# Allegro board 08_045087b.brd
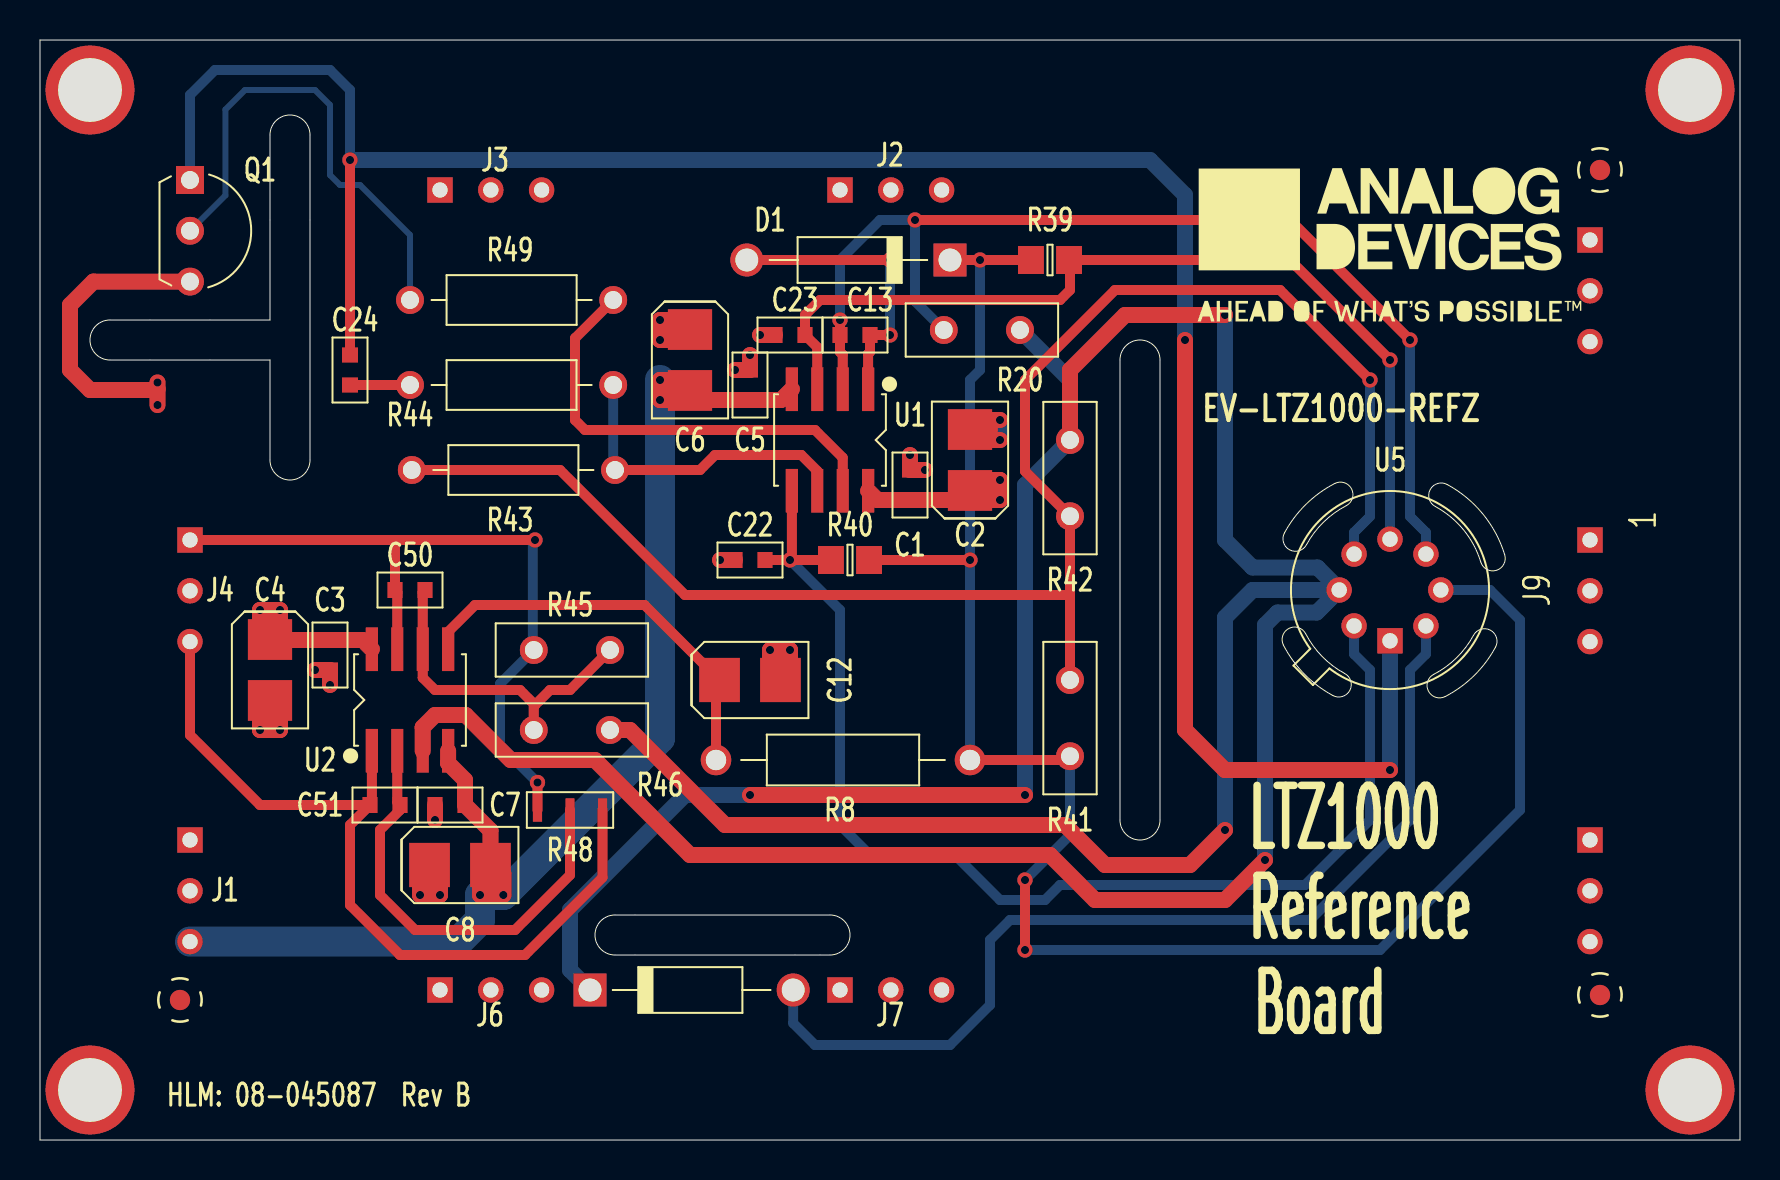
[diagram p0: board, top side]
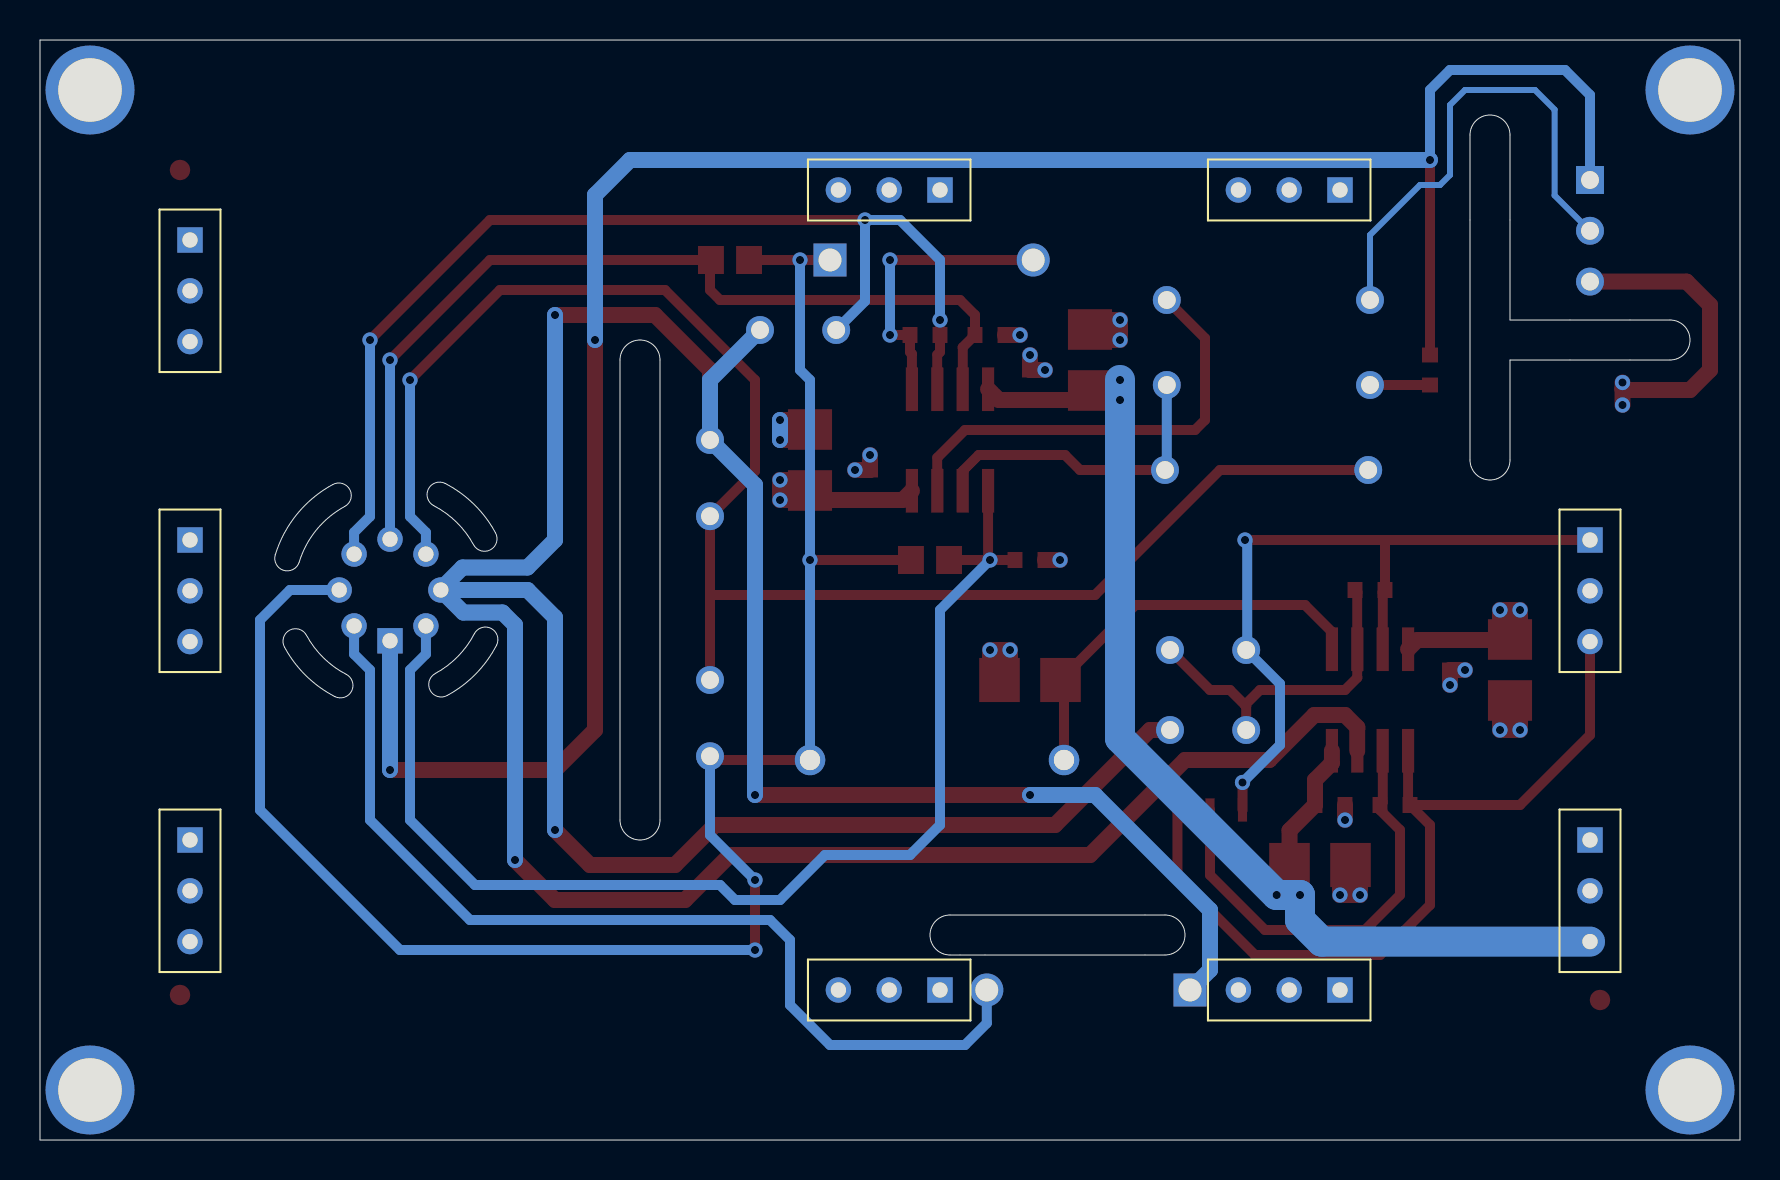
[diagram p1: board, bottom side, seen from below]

Outline 85 x 55 mm; copper layers: TOP, LAYER2, LAYER3, BOTTOM. Coordinates in mm from the lower left corner of the outline.
Outline path: 0,55 0,0 85,0 85,55 0,55 ; 3.5,39 arc(2.5,40) 3.5,41 11.5,41 11.5,50.25 arc(12.5,51.25) 13.5,50.25 13.5,34 arc(13.21,33.29) 12.5,33 arc(11.79,33.29) 11.5,34 11.5,39 3.5,39 ; 28.75,11.25 39.5,11.25 arc(40.5,10.25) 39.5,9.25 28.75,9.25 arc(27.75,10.25) 28.75,11.25 ; 54,39 54,16 arc(54.29,15.29) 55,15 arc(55.71,15.29) 56,16 56,39 arc(55.71,39.71) 55,40 arc(54.29,39.71) 54,39 ; 62.17,24.74 arc(62.44,25.58) 63.28,25.31 arc(64.11,24.17) 65.24,23.32 arc(65.49,22.48) 64.64,22.22 arc(63.22,23.3) 62.17,24.74 62.17,24.74 ; 62.22,30.36 arc(63.3,31.78) 64.74,32.83 64.74,32.83 arc(65.58,32.56) 65.31,31.72 arc(64.17,30.89) 63.32,29.76 arc(62.48,29.51) 62.22,30.36 ; 69.76,31.68 arc(69.51,32.52) 70.36,32.78 arc(72.14,31.3) 73.23,29.26 arc(72.82,28.48) 72.04,28.9 arc(71.17,30.51) 69.76,31.68 ; 70.26,22.17 arc(69.42,22.44) 69.69,23.28 arc(70.83,24.11) 71.68,25.24 arc(72.52,25.49) 72.78,24.64 arc(71.7,23.22) 70.26,22.17 70.26,22.17

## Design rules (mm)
constraint set DEFAULT: min track width 0.19

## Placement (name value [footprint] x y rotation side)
C1  0.1UF  [C0603]  43.5 32.75 270 top
C2  10uF  [C3528]  46.5 34 90 top
C3  0.1UF  [C0603]  14.5 24.25 90 top
C4  10uF  [C3528]  11.5 23.5 270 top
C5  0.1UF  [C0603]  35.5 37.75 90 top
C6  10uF  [C3528]  32.5 39 270 top
C7  0.1UF  [C0603]  20.5 16.75 180 top
C8  10uF  [C3528]  21 13.75 0 top
C12  10uF  [C3528]  35.5 23 0 top
C13  0.1UF  [C0603]  40.75 40.25 0 top
C22  0.1UF  [C0603]  35.5 29 0 top
C23  0.1UF  [C0603]  37.5 40.25 0 top
C24  0.1UF  [C0603]  15.5 38.5 90 top
C50  0.1UF  [C0603]  18.5 27.5 180 top
C51  0.1UF  [C0603]  17.25 16.75 180 top
D1  1N270  [DO35]  45.5 44 180 top
D2  1N270  [DO35]  27.5 7.5 0 top
J1  350-10-103-00-006000  [CNTHMHDR1X3L300W100H284]  7.5 15 270 bottom
J2  350-10-103-00-006000  [CNTHMHDR1X3L300W100H284]  40 47.5 0 bottom
J3  350-10-103-00-006000  [CNTHMHDR1X3L300W100H284]  20 47.5 0 bottom
J4  310-13-103-41-001000  [CNTHFHDR1X3L300W100H165]  7.5 30 270 bottom
J5  310-13-103-41-001000  [CNTHFHDR1X3L300W100H165]  77.5 45 270 bottom
J6  310-13-103-41-001000  [CNTHFHDR1X3L300W100H165]  20 7.5 0 bottom
J7  350-10-103-00-006000  [CNTHMHDR1X3L300W100H284]  40 7.5 0 bottom
J8  350-10-103-00-006000  [CNTHMHDR1X3L300W100H284]  77.5 15 270 bottom
J9  350-10-103-00-006000  [CNTHMHDR1X3L300W100H284]  77.5 30 270 bottom
NOREF  -  []  55 15 90 top
NOREF#2  -  [unnamed#2]  82.5 52.5 0 top
NOREF#3  -  []  0 55 0 top
NOREF#4  -  []  -100 -90 0 top
NOREF#5  -  []  54 39 0 top
NOREF#6  -  []  28.75 9.25 90 top
NOREF#7  -  []  -95 -90 0 top
NOREF#8  -  [unnamed#2]  82.5 2.5 0 top
NOREF#9  -  []  27.75 10.25 0 top
NOREF#10  -  [unnamed#2]  78 7.25 0 top
NOREF#11  -  [unnamed#2]  2.5 52.5 0 top
NOREF#12  -  []  11.5 46 0 top
NOREF#13  -  [unnamed#2]  2.5 2.5 0 top
NOREF#14  -  [unnamed#2]  78 48.5 0 top
NOREF#15  -  []  41.75 -11.25 0 top
NOREF#16  -  []  0 0 90 top
NOREF#17  -  []  67.5 44.75 0 top
NOREF#18  -  [unnamed#2]  7 7 0 top
Q1  2N3904TF  [TO92V2]  7.5 48 270 top
R8  1.5K  [RN55]  46.5 19 180 top
R20  120  [RRADTH150L300H336W105LD25]  49 40.5 180 top
R39  68K  [R0805]  50.5 44 180 top
R40  68K  [R0805]  40.5 29 0 top
R41  15K  [RRADTH150L300H336W105LD25]  51.5 23 270 top
R42  1K  [RRADTH150L300H336W105LD25]  51.5 35 270 top
R43  10K  [MRS25]  28.75 33.5 180 top
R44  1MEG  [MRS25]  18.5 37.75 0 top
R45  10K  [RRADTH150L300H336W105LD25]  28.5 24.5 180 top
R46  25K  [RRADTH150L300H336W105LD25]  28.5 20.5 180 top
R48  10K/10K  [R1505_A]  26.5 16.5 0 top
R49  1K  [MRS25]  18.5 42 0 top
U1  ADA4077-2BRZ  [SO8]  39.5 35 180 top
U2  ADA4077-2BRZ  [SO8]  18.5 22 0 top
U5  LTZ1000ACH#PBF  [TO5-8P]  67.5 27.5 180 top

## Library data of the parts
C1 C3 C5 C7 C13 C22-C24 C50 C51 = CAP: User Part Number: UPN; Tolerance: 10; alternate symbols: (); part number: CAP_SM-0.1UF,25V,10,E007204,C0603; tolerance: 10
C2 C4 C6 C8 C12 = CAPP: User Part Number: UPN; Tolerance: N/A; alternate symbols: (); part number: CAPP_SM-10UF,N/A,N/A,E000695,C3528; tolerance: N/A
D1 D2 = DIO: Tolerance: N/A; User Part Number: UPN; alternate symbols: (); part number: DIO_TH-1N270,N/A,N/A,E001093,DO35; tolerance: N/A
J1-J3 J7-J9 = CN3P: User Part Number: UPN; Tolerance: N/A; alternate symbols: (); part number: CN3P_TH-350-10-103-00-006000,E027762,CNTHMHDR1X3L300W100H284; tolerance: N/A
J4-J6 = CN3P: User Part Number: UPN; Tolerance: N/A; alternate symbols: (); part number: CN3P_TH-310-13-103-41-001000,E027752,CNTHFHDR1X3L300W100H165; tolerance: N/A
Q1 = TRAN2N3904: User Part Number: UPN; Tolerance: N/A; alternate symbols: (); part number: TRAN2N3904_TH-2N3904TF,E017741,TO92V2; tolerance: N/A
R8 = RES: Tolerance: 1; User Part Number: UPN; alternate symbols: (); part number: RES_TH-1.5K,E002827,1/4W,1,RN55; tolerance: 1
R20 = RES: Tolerance: 0.01; User Part Number: UPN; alternate symbols: (); part number: RES_TH-120,E024765,3/5W,0.01,RRADTH150L300H336W105LD25; tolerance: 0.01
R39 R40 = RES: User Part Number: UPN; Tolerance: 0.1; alternate symbols: (R0805L); part number: RES_SM-68K,E024854,1/10W,0.1,R0805; tolerance: 0.1
R41 = RES: Tolerance: 0.01; User Part Number: UPN; alternate symbols: (); part number: RES_TH-15K,E024961,3/5W,0.01,RRADTH150L300H336W105LD25; tolerance: 0.01
R42 = RES: Tolerance: 0.01; User Part Number: UPN; alternate symbols: (); part number: RES_TH-1K,E024763,3/5W,0.01,RRADTH150L300H336W105LD25; tolerance: 0.01
R43 = RES: Tolerance: 1; User Part Number: UPN; alternate symbols: (); part number: RES_TH-10K,E012142,3/5W,1,MRS25; tolerance: 1
R44 = RES: Tolerance: 1; User Part Number: UPN; alternate symbols: (); part number: RES_TH-1MEG,E010720,3/5W,1,MRS25; tolerance: 1
R45 = RES: Tolerance: 0.005; User Part Number: UPN; alternate symbols: (); part number: RES_TH-10K,E018578,6/10W,0.005,RRADTH150L300H336W105LD25; tolerance: 0.005
R46 = RES: Tolerance: 0.01; User Part Number: UPN; alternate symbols: (); part number: RES_TH-25K,E024766,3/5W,0.01,RRADTH150L300H336W105LD25; tolerance: 0.01
R48 = RES3P_V2: User Part Number: UPN; Tolerance: 0.01; alternate symbols: (); part number: RES3P_V2_SM-10K/10K,E024769,1/10W,0.01,R1505_A; tolerance: 0.01
R49 = RES: Tolerance: 1; User Part Number: UPN; alternate symbols: (); part number: RES_TH-1K,E011314,3/5W,1,MRS25; tolerance: 1
U1 U2 = ADA4077_2: User Part Number: UPN; Tolerance: N/A; alternate symbols: (); part number: ADA4077_2_SM-ADA4077-2BRZ,E018506,SO8; tolerance: N/A
U5 = LINLTZ1000: User Part Number: UPN; Tolerance: N/A; alternate symbols: (); part number: LINLTZ1000_TH-LTZ1000ACH#PBF,E010783,TO5-8P; tolerance: N/A

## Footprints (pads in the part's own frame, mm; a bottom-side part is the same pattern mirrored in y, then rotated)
C0603
  rect 0.75x0.8 smd: 1(-0.75,0) 2(0.75,0)
C3528
  rect 2.032x2.21 smd: N(1.524,0) P(-1.524,0)
CNTHFHDR1X3L300W100H165
  rect 1.27x1.27 hole 0.762: 1(0,0)
  round 1.27 hole 0.762: 2(2.54,0) 3(5.08,0)
CNTHMHDR1X3L300W100H284
  rect 1.27x1.27 hole 0.762: 1(0,0)
  round 1.27 hole 0.762: 2(2.54,0) 3(5.08,0)
DO35
  round 1.651 hole 1.143: A(10.16,0)
  rect 1.651x1.651 hole 1.143: C(0,0)
MRS25
  round 1.397 hole 0.889: 1(0,0) 2(10.16,0)
R0805
  rect 1.295x1.397 smd: 1(-0.953,0) 2(0.953,0)
R1505_A
  rect 0.457x1.168 smd: 1(-1.626,0) 2(0,0) 3(1.626,0)
RN55
  round 1.524 hole 1.016: 1(0,0) 2(12.7,0)
RRADTH150L300H336W105LD25
  round 1.397 hole 0.889: 1(0,0) 2(3.81,0)
SO8
  rect 0.61x2.184 smd: 1(-1.905,-2.54) 2(-0.635,-2.54) 3(0.635,-2.54) 4(1.905,-2.54) 5(1.905,2.54) 6(0.635,2.54) 7(-0.635,2.54) 8(-1.905,2.54)
TO5-8P
  rect 1.27x1.27 hole 0.762: 1(0,2.54)
  round 1.27 hole 0.762: 2(-1.796,1.796) 3(-2.54,0) 4(-1.796,-1.796) 5(0,-2.54) 6(1.796,-1.796) 7(2.54,0) 8(1.796,1.796)
TO92V2
  rect 1.397x1.397 hole 0.889: 1(0,0)
  round 1.397 hole 0.889: 2(2.54,0) 3(5.08,0)
unnamed#2
  round 4.445 hole 3.175 unplated: (0,0)

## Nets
AGND: C1.1(N1) C2.N(N2) C3.1(N1) C4.N(N2) C5.2(N2) C6.P(N1) C7.2(N2) C8.P(N1) C12.N(N2) C22.1(N1) C23.1(N1) D2.C(N) J1.2(N2) J4.2(N2) R20.1(N1) R42.1(N1) R46.1(N1) U2.3(+IN) U5.7(N7)
VDD: C1.2(N2) C2.P(N1) C3.2(N2) C4.P(N1) J1.1(N1) Q1.3(C) U1.8(V+) U2.8(V+)
VSS: C5.1(N1) C6.N(N2) C7.1(N1) C8.N(N2) J1.3(N3) U1.4(V-) U2.4(V-)
UNNAMED_2_ADA40772_I96_: C50.1(N1) R45.1(N1) R46.2(N2) U2.6(-IN)
UNNAMED_2_ADA40772_I96__1: C12.P(N1) R8.2(N2) U2.5(+IN)
UNNAMED_2_ADA40772_I97_: C51.1(N1) R48.2(N2) U2.2(-IN)
UNNAMED_2_ADA40772_I100_: C22.2(N2) R40.1(N1) U1.5(+IN) U5.8(N8)
UNNAMED_2_ADA40772_I100__1: R43.1(N1) R44.2(N2) U1.6(-IN)
UNNAMED_2_ADA40772_I100_OUT: R49.2(N2) U1.7(OUT)
UNNAMED_2_ADA40772_I101_: C23.2(N2) R39.1(N1) U1.3(+IN) U5.5(N5)
UNNAMED_2_ADA40772_I101__1: C13.1(N1) R20.2(N2) U1.2(-IN) U5.4(N4)
UNNAMED_2_ADA40772_I101_OUT: C13.2(N2) D1.A(P) U1.1(OUT)
UNNAMED_2_CAP_I20_N1: C24.1(N1) R44.1(N1)
UNNAMED_2_CAP_I20_N2: C24.2(N2) Q1.1(E) U5.1(N1)
UNNAMED_2_DIO_I28_P: D2.A(P) U5.2(N2)
UNNAMED_2_DIO_I48_N: D1.C(N) R8.1(N1) R39.2(N2) R40.2(N2) R41.2(N2) U5.3(N3)
UNNAMED_2_LINLTZ1000_I30_N6: R41.1(N1) R42.2(N2) R43.2(N2) U5.6(N6)
UNNAMED_2_RES_I21_N1: Q1.2(B) R49.1(N1)
VREFN: C51.2(N2) J4.3(N3) R48.3(N3) U2.1(OUT)
VREFP: C50.2(N2) J4.1(N1) R45.2(N2) R48.1(N1) U2.7(OUT)

Pads without a net: J2 1 2 3; J3 1 2 3; J5 1 2 3; J6 1 2 3; J7 1 2 3; J8 1 2 3; J9 1 2 3

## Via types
v1: diameter 0.762, hole 0.406, TOP to BOTTOM, 51 vias

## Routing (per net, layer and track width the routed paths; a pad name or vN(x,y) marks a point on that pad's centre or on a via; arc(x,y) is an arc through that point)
AGND: length 239.8
  TOP w0.8: C23.1 v1(36,40.25) ; U2.3 19.14,20.64 19.75,21.25 21.28,21.25 23.53,19 27.75,19 32.5,14.25 50.5,14.25 52.75,12 59.25,12 v1(61.25,14) ; 37,23.5 37.45,23.5 37.5,23.55 v1(37.5,24.5) v1(36.5,24.5) 36.5,23.55 36.55,23.5 37,23.5 ; 37,23.5 37.02,23.48 C12.N ; 11.5,21.25 11.95,21.25 12,21.2 v1(12,20.5) v1(11,20.5) 11,21.2 11.05,21.25 11.5,21.25 ; 11.5,21.25 C4.N ; v1(14.5,22.75) C3.1 v1(13.75,23.5) ; C7.2 v1(19.75,16) ; v1(59.25,15.5) 57.5,13.75 53.25,13.75 51.25,15.75 34.25,15.75 29.5,20.5 R46.1 ; 19.36,13.56 19.36,13.64 C8.P ; 19.36,13.56 19,13.2 v1(19,12.25) v1(20,12.25) 20,12.93 19.36,13.56 ; 31.52,40.52 C6.P ; 31.52,40.52 31.52,40.05 31.47,40 v1(31,40) v1(31,41) 31.47,41 31.52,40.95 31.52,40.52 ; 47.48,35.52 47.48,35.05 47.53,35 v1(48,35) ; 47.48,35.52 47.48,35.95 47.53,36 v1(48,36) ; 47.48,35.52 C2.N ; R42.1 51.5,38.5 54.25,41.25 v1(59.25,41.25) ; v1(35.5,39.25) C5.2 v1(34.75,38.5) ; v1(49.25,17.25) v1(35.5,17.25) ; v1(43.5,34.25) C1.1 v1(44.25,33.5) ; C22.1 v1(34,29)
  LAYER2 w0.39: J4.2 7.5,28.4 ; J4.2 6.56,27.46 ; J4.2 7.5,26.52 ; J4.2 8.44,27.46 ; R20.1 50,40.5 ; R20.1 49,39.5 ; R20.1 49,41.5 ; R20.1 48,40.5 ; 6.56,12.46 J1.2 ; J1.2 7.5,11.52 ; J1.2 8.44,12.46 ; J1.2 7.5,13.4
  BOTTOM w0.8: v1(48,36) v1(48,35) ; D2.C 26.5,8.5 26.5,11.5 32.25,17.25 v1(35.5,17.25) ; v1(61.25,14) 61.25,25.75 61.88,26.38 63.84,26.38 U5.7 ; U5.7 64.96,27.54 63.88,28.62 60.62,28.62 59.25,30 v1(59.25,41.25) ; U5.7 60.62,27.5 59.25,26.12 v1(59.25,15.5) ; R20.1 51.5,38 R42.1 49.25,32.75 v1(49.25,17.25)
VDD: length 38.5
  TOP w0.8: 5.88,37.55 5.83,37.5 2.5,37.5 1.5,38.5 1.5,41.75 2.67,42.92 Q1.3 ; 5.88,37.55 v1(5.88,36.75) ; 5.88,37.55 v1(5.88,37.88) ; 47.27,32.48 47.27,32.05 47.32,32 v1(48,32) v1(48,33) 47.32,33 47.27,32.95 47.27,32.48 ; 47.27,32.48 C2.P 46.02,32 C1.2 41.87,32 U1.8 ; 11.5,25.75 11.95,25.75 12,25.8 v1(12,26.5) v1(11,26.5) 11,25.8 11.05,25.75 11.5,25.75 ; 11.5,25.75 C4.P 11.52,25 C3.2 16.14,25 U2.8
  LAYER3 w0.39: J1.1 8.44,15 ; J1.1 6.56,15 ; J1.1 7.5,14.06 ; J1.1 7.5,15.94
VSS: length 67.6
  TOP w0.8: U1.4 37.05,37 C5.1 32.98,37 C6.N 31.73,37.48 ; 22.16,13.38 C8.N 22.52,15.48 C7.1 21.25,18 20.41,18.84 U2.4 ; 22.16,13.38 22,13.23 v1(22,12.25) v1(23.17,12.25) 23.17,13.33 23.12,13.38 22.16,13.38 ; 31.73,37.48 31.73,37.05 31.68,37 v1(31,37) v1(31,38) 31.68,38 31.73,37.95 31.73,37.48
  BOTTOM w1.5: v1(31,38) v1(31,37) 31,20.08 v1(23.17,12.25) v1(22,12.25) 22,11 20.92,9.92 J1.3
UNNAMED_2_ADA40772_I96_: length 16.8
  TOP w0.5: C50.1 19.14,27.39 U2.6 19.14,23.11 19.75,22.5 24,22.5 24.75,21.75 ; 24.75,21.75 25.5,22.5 26.5,22.5 R45.1 ; 24.75,21.75 24.69,21.69 R46.2
UNNAMED_2_ADA40772_I96__1: length 20.6
  TOP w0.5: U2.5 20.41,25.41 21.75,26.75 30.23,26.75 C12.P 33.8,22.82 R8.2
UNNAMED_2_ADA40772_I97_: length 22.3
  TOP w0.5: U2.2 17.86,16.89 C51.1 18,16.5 17,15.5 17,12.25 18.75,10.5 23.75,10.5 26.5,13.25 R48.2
UNNAMED_2_ADA40772_I100_: length 60.8
  TOP w0.5: U1.5 37.59,29.09 v1(37.5,29) ; v1(37.5,29) R40.1 ; v1(37.5,29) C22.2
  BOTTOM w0.5: U5.8 65.7,24.3 66.5,23.5 66.5,16 63.25,12.75 51,12.75 50.25,12 48,12 45.75,14.25 41.5,14.25 40,15.75 40,26.5 v1(37.5,29)
UNNAMED_2_ADA40772_I100__1: length 16
  TOP w0.5: U1.6 38.87,33.45 38.06,34.25 33.75,34.25 33,33.5 R43.1
  BOTTOM w0.5: R43.1 28.66,33.59 R44.2
UNNAMED_2_ADA40772_I100_OUT: length 22.6
  TOP w0.5: R49.2 26.75,40.09 26.75,36 27.25,35.5 38.75,35.5 40.13,34.12 U1.7
UNNAMED_2_ADA40772_I101_: length 46.3
  TOP w0.5: v1(67.5,39) 62.5,44 R39.1 51.5,43.95 51.5,42.5 51,42 39,42 38.25,41.25 C23.2 38.87,39.63 U1.3
  BOTTOM w0.5: v1(67.5,39) U5.5
UNNAMED_2_ADA40772_I101__1: length 55.5
  TOP w0.5: v1(68.5,40) 62.5,46 v1(43.75,46) ; v1(40,41) C13.1 40,39.4 40.13,39.27 U1.2
  BOTTOM w0.5: U5.4 69.3,30.38 68.5,31.18 v1(68.5,40) ; v1(40,41) 40,44 42,46 v1(43.75,46) 43.75,41.94 R20.2
UNNAMED_2_ADA40772_I101_OUT: length 14.7
  TOP w0.5: v1(42.5,44) D1.A ; U1.1 41.41,39.3 41.5,39.4 C13.2 v1(42.5,40.25)
  BOTTOM w0.5: v1(42.5,40.25) v1(42.5,44)
UNNAMED_2_CAP_I20_N1: length 3
  TOP w0.5: C24.1 R44.1
UNNAMED_2_CAP_I20_N2: length 113.2
  TOP w0.5: C24.2 v1(15.5,49)
  TOP w0.8: v1(57.25,40) 57.25,20.5 59.25,18.5 v1(67.5,18.5)
  BOTTOM w0.5: v1(15.5,49) 15.5,52.5 14.5,53.5 8.75,53.5 7.5,52.25 Q1.1
  BOTTOM w0.8: U5.1 v1(67.5,18.5) ; v1(15.5,49) 55.5,49 57.25,47.25 v1(57.25,40)
UNNAMED_2_DIO_I28_P: length 49.5
  BOTTOM w0.5: U5.2 69.3,24.3 68.5,23.5 68.5,16 63.5,11 48.5,11 47.5,10 47.5,6.75 45.5,4.75 38.75,4.75 37.66,5.84 D2.A
UNNAMED_2_DIO_I48_N: length 91.7
  TOP w0.5: R41.2 51.31,19 R8.1 ; v1(49.25,13) v1(49.25,9.5) ; R39.2 v1(47,44) D1.C ; R40.2 v1(46.5,29)
  BOTTOM w0.5: v1(49.25,9.5) 67,9.5 74,16.5 74,26 72.5,27.5 U5.3 ; v1(49.25,13) 51.5,15.25 R41.2 ; v1(47,44) 47,38.5 46.5,38 v1(46.5,29) R8.1
UNNAMED_2_LINLTZ1000_I30_N6: length 81.4
  TOP w0.5: v1(66.5,38) 62,42.5 53.75,42.5 49.25,38 49.25,33.44 R42.2 51.5,27.25 ; 51.5,27.25 R41.1 ; 51.5,27.25 32.25,27.25 26,33.5 R43.2
  BOTTOM w0.5: U5.6 65.7,30.38 66.5,31.18 v1(66.5,38)
UNNAMED_2_RES_I21_N1: length 24.7
  BOTTOM w0.3: R49.1 18.5,45.25 16,47.75 15,47.75 14.5,48.25 14.5,51.75 13.75,52.5 10.25,52.5 9.27,51.52 9.27,47.23 Q1.2
VREFN: length 41.9
  TOP w0.5: R48.3 28.13,13.13 24.25,9.25 18,9.25 15.5,11.75 15.5,15.75 C51.2 ; C51.2 11,16.75 7.5,20.25 J4.3 ; C51.2 16.59,16.84 U2.1
VREFP: length 37.8
  TOP w0.5: R48.1 v1(24.87,17.88) ; 17.75,30 C50.2 17.86,27.39 U2.7 ; 17.75,30 v1(24.75,30) ; 17.75,30 J4.1
  BOTTOM w0.5: v1(24.87,17.88) 23,19.75 23,22.81 R45.2 24.64,24.55 24.64,29.89 v1(24.75,30)

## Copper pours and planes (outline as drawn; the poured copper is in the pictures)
AGND on LAYER2: 5.5,5.5 5.5,38.5 14,38.5 14,47.5 53.5,47.5 53.5,38.25 49.25,38.25 49.25,18 48.5,17.25 49.25,16.5 49.25,5.5 41,5.5 41,10.25 40.56,11.31 39.5,11.75 26,11.75 26,5.5 ; 2 cut-outs
VDD on LAYER3: 5.5,38.5 5.5,5.5 26,5.5 26,11.75 39.5,11.75 40.56,11.31 41,10.25 41,5.5 49.25,5.5 49.25,38.25 53.5,38.25 53.5,47.5 14,47.5 14,38.5

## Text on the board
Ref Des/Silkscreen Top: HLM: 08-045087  Rev B | EV-LTZ1000-REFZ | LTZ1000 | Reference | Board
LAYER2: L2 Internal GND | 08-      -07
LAYER3: L3 Internal PWR | 08-      -08
XSECTION_CHART: Primary Side Silkscreen | Primary Side Soldermask | 0.035 (1oz) Copper Plating | Primary side 0.017 (0.5oz) Copper Foil | FR4 Prepreg | 0.035 (1oz) Copper | Secondary Side 0.017 (0.5oz) Copper Foil | FR4 CORE | Secondary Side Soldermask | Secondary side Silkscreen | 1.6mm +/-10% | 4 LAYER STACKUP
User.20: LTZ1000 REFERENCE BRD
User.23: 10. Manufacturer UL and Date codes on the bottom side silkscreen as indicated. | 1. Material: 4 Layer FR4 glass epoxy laminate 1.6mm +/- 10%. material to be RoHS compliant. | 2. Plated thru holes and conductive pattern electroplated with 0.255mm min. thick copper. | 3. Processing tolerence: | 4. Warp and twist within 0.1875mm per 25mm (0.75%) | 5. Dimensions are for the finished part. | 6. SOLDERMASK: liquid Photo Imeagable soldermask over bare copper (SMOBC), | 7. SCREENING: Screen component outlines and nomenclature using indelible white ink on both sides. | 8. Electrically test 100%. | 9. Break all sharp edges 0.35mm Radius max. | Board to be fabricated per IPC-6012A, CLASS 2. | Terminal areas and plated thru holes to be ENIG plated. | colour GREEN both sides using the pattern provided. No mask is permitted on the terminal areas. | Soldermask to etch registration within 0.125mm total. | A. Conductive pattern front to back registration within 0.125mm total. | B. Minimum annual ring surrounding holes 0.05mm. | C. Finished conductive pattern to be within 0.05mm of true size. | D. Minimumfeature size 0.2mm | E. Minimum air gap 0.12mm | Nomenclature shall be legible. Screen to etch registration within 0.15mm total. | FABRICATION NOTES: | CUTOUT | ROUTE WIDTH | FOLLOW | CUTOUTS X4 | OUTLINE | 1.25MM | 1 | FABRICATION | 09-045087-01 | B
